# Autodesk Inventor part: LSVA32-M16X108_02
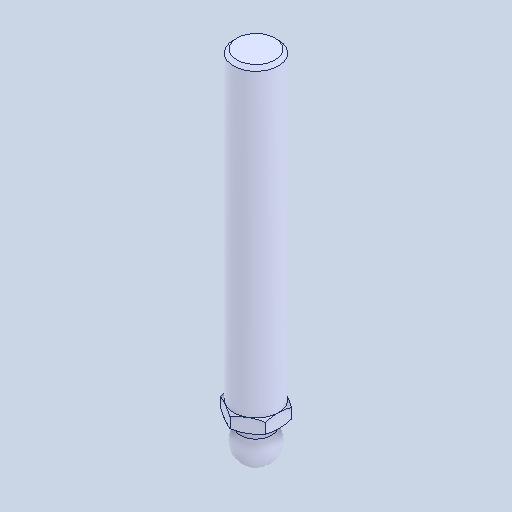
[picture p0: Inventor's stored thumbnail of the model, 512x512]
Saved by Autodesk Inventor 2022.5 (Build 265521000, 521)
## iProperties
Created: 2024-08
Part Number: LSVA32-M16X108_02
Material: 一般
Document SubType Name: Modeling
Designer: ImaoCorp
Density: 1 g/cm^3
Appearance: 既定
Author: ImaoCorp
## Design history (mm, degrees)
feature "LSVA32-M16X108_02"
node "ソリッド1"
